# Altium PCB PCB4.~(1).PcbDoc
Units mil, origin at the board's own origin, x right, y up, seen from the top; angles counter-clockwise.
Board outline 6000 x 4000 mil, 2 copper layers (Top Layer, Bottom Layer); 86 components, 57 nets, 223 pads, 2 vias.
Unrouted connection lines stored in the file: 90.
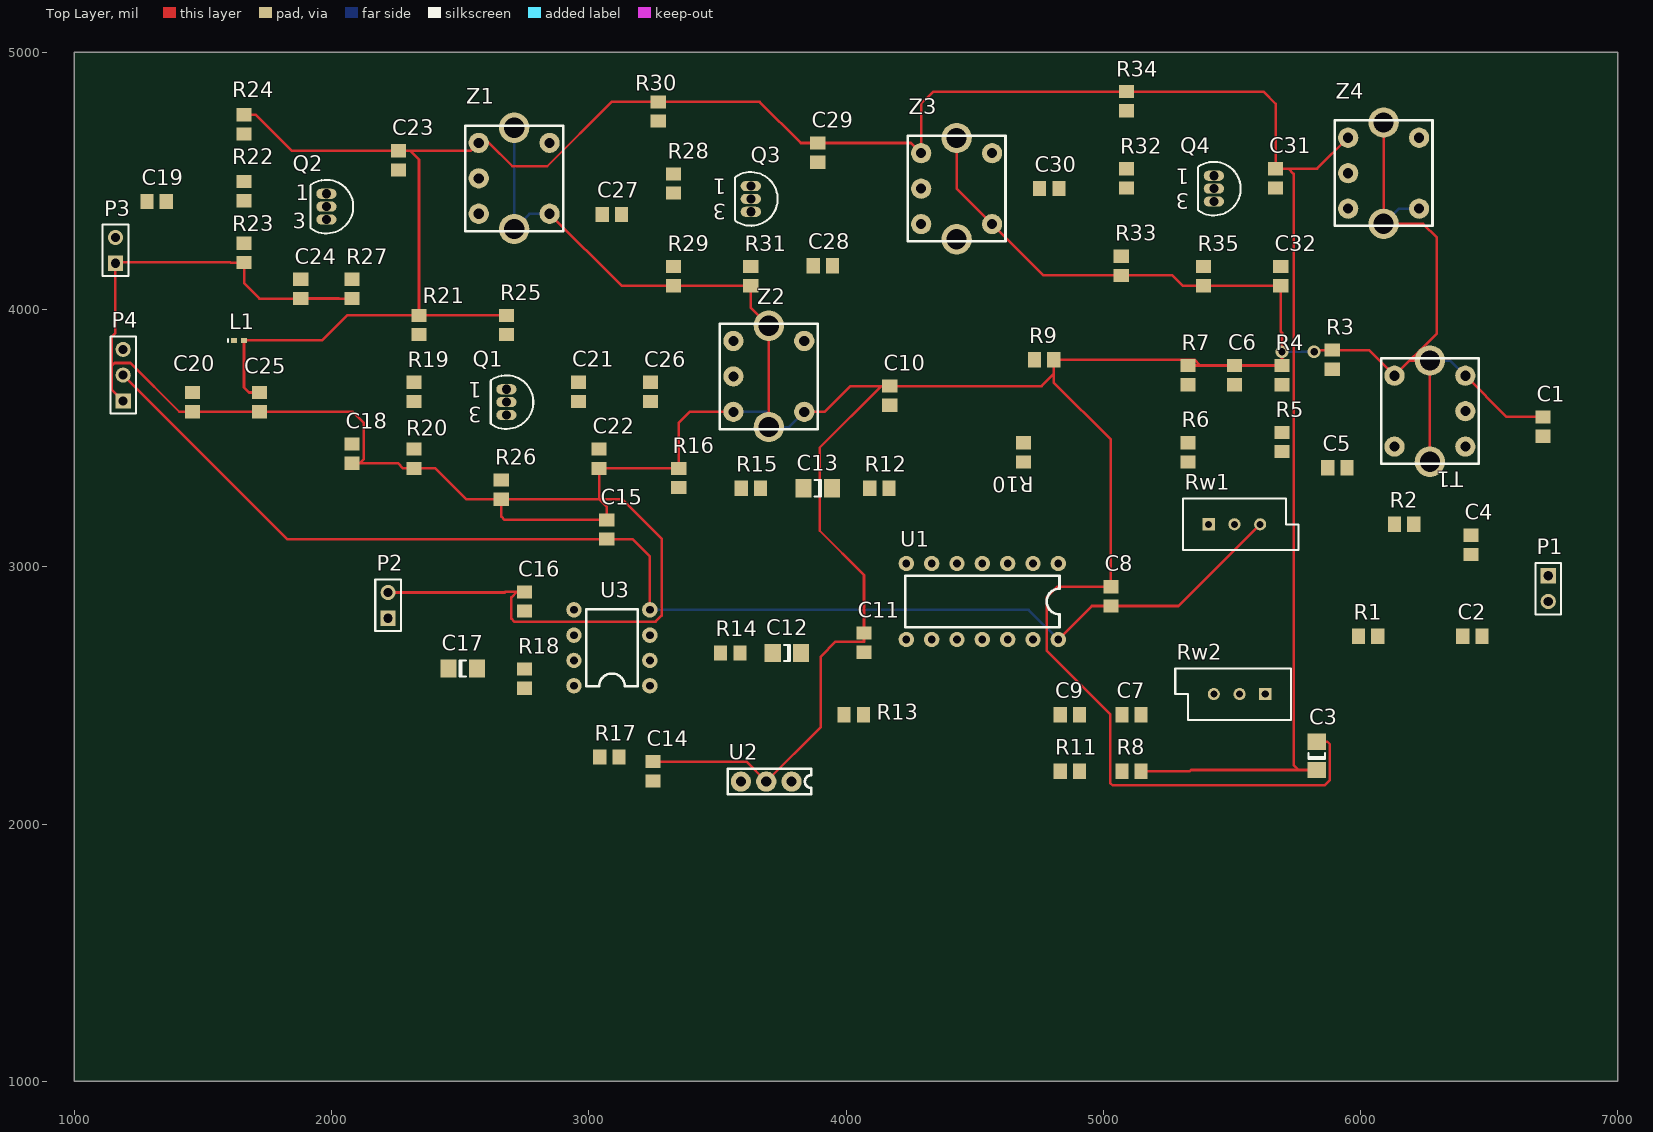
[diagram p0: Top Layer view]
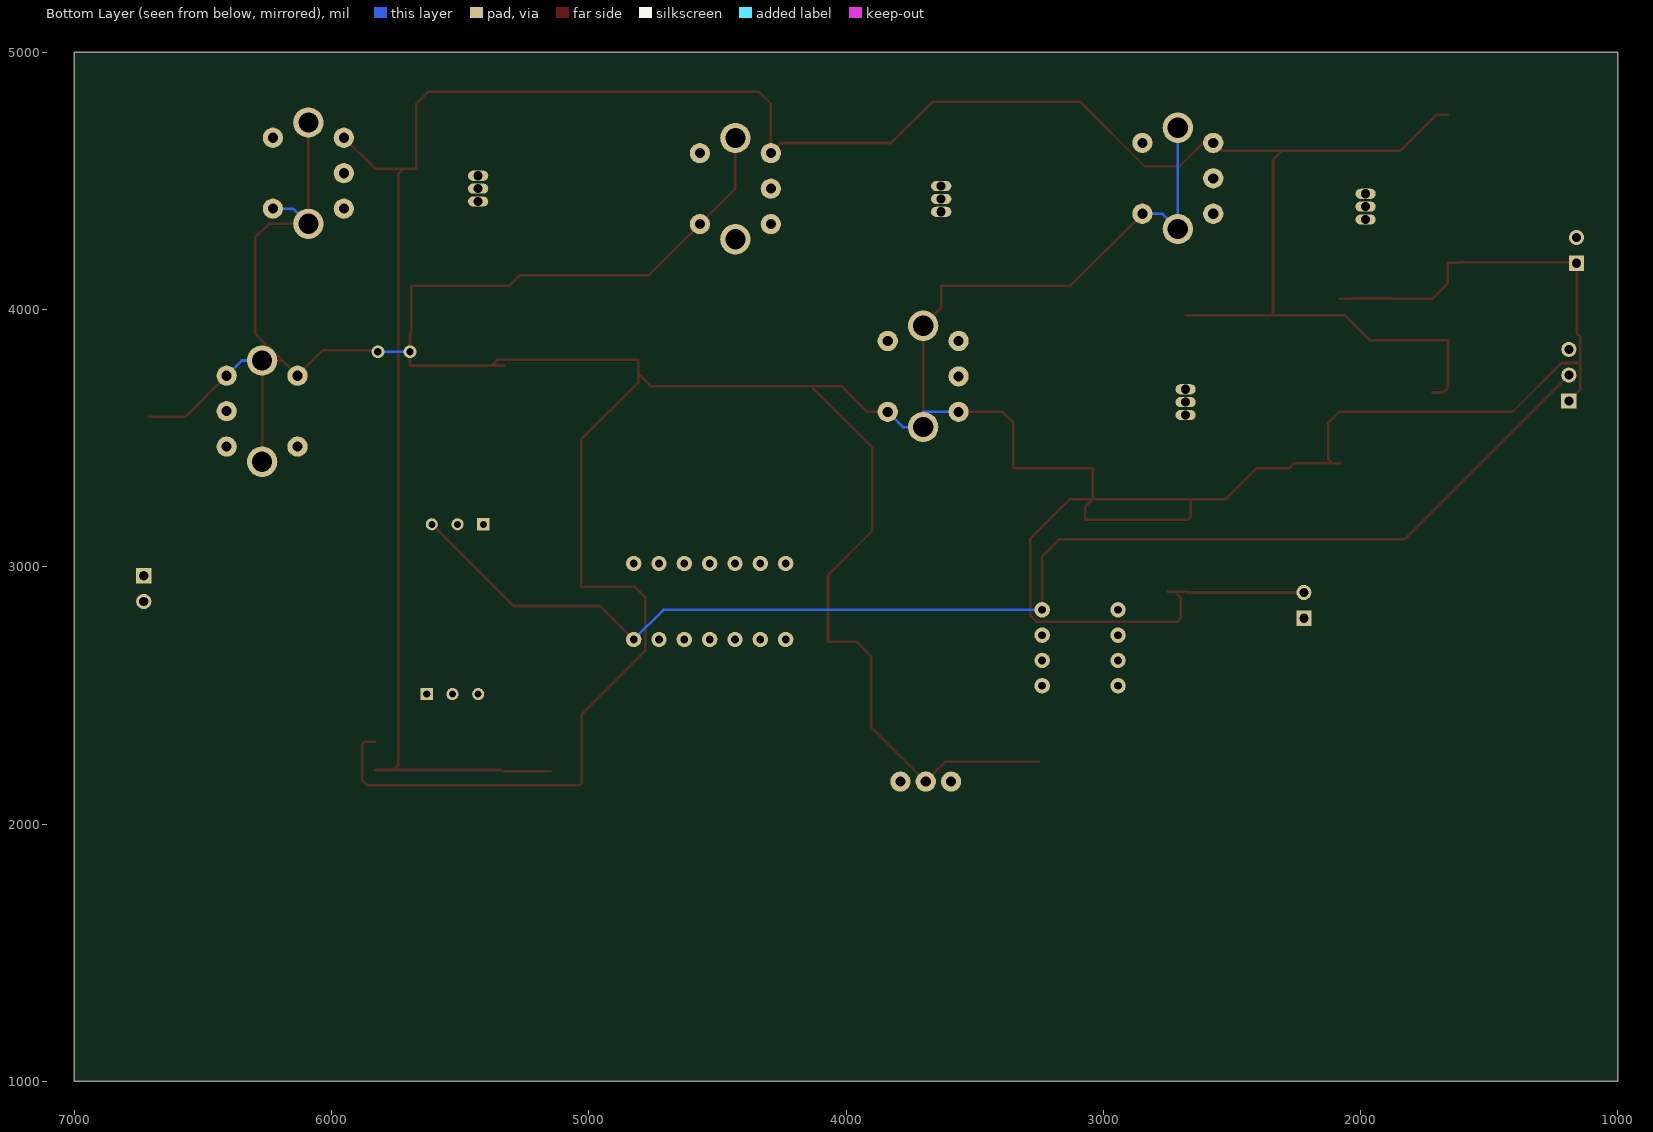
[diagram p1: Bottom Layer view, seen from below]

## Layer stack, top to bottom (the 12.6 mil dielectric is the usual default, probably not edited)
Top Layer: signal copper 1.4
Dielectric: dielectric 12.6, FR-4, Dk 4.8
Bottom Layer: signal copper 1.4

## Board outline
1000,1000 7000,1000 7000,5000 1000,5000

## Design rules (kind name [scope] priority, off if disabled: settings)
Clearance [All] p1: gap=10
PolygonConnect [All] p1: connectstyle=Relief reliefconductorwidth=10 reliefentries=4 polygonreliefangle="90 Angle"
RoomDefinition Sheet1 [InComponentClass('Sheet1')] p1: confinementstyle=ConfineIn formatcopy=TRUE lockcomponents=FALSE outline 0,0 2000,0 2000,1000 0,1000
RoomDefinition Sheet2 [InComponentClass('Sheet2')] p2: confinementstyle=ConfineIn formatcopy=TRUE lockcomponents=FALSE outline 0,0 2000,0 2000,1000 0,1000
RoutingVias [All] p1: holewidth=28 width=50 viastyle="Through Hole" minholewidth=28 minwidth=50 maxholewidth=28 maxwidth=50
SilkscreenOverComponentPads [All] p1: minsilkscreentomaskgap=10
SolderMaskExpansion [All] p1: expansion=4
TestPointUsage [All] p1: valid=0 allowmultiple=FALSE
Testpoint [All] p1: side=15 testpointundercomponent=TRUE minsize=40 maxsize=100 preferedsize=60 minholesize=0 maxholesize=40 preferedholesize=32 testpointgrid=1 style=1023 order=0123456789
Width [All] p1: maxlimit=10 minlimit=10 preferedwidth=10
23 further rules are at their usual default settings.

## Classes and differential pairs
component class Sheet2: C18 C19 C20 C21 C22 C23 C24 C25 C26 C27 C28 C29 C30 C31 C32 L1 P3 P4 Q1 Q2 Q3 Q4 R19 R20 R21 R22 R23 R24 R25 R26 R27 R28 R29 R30 R31 R32 R33 R34 R35 Z1 Z2 Z3 Z4
component class Sheet1: C1 C2 C3 C4 C5 C6 C7 C8 C9 C10 C11 C12 C13 C14 C15 C16 C17 P1 P2 R1 R2 R3 R4 R5 R6 R7 R8 R9 R10 R11 R12 R13 R14 R15 R16 R17 R18 Rw1 Rw2 T1 U1 U2 U3

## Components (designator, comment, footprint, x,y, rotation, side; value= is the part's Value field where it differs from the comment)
C1 "Cap" 2012[0805] 6710,3545 r270 top
C2 "Cap" 2012[0805] 6435,2730 r180 top
C3 "Cap Pol1" C1206 5830,2265 r90 top
C4 "Cap" 2012[0805] 6430,3085 r270 top
C5 "Cap" 2012[0805] 5910,3385 r180 top
C6 "Cap" 2012[0805] 5510,3745 r270 top
C7 "Cap" 2012[0805] 5110,2425 r180 top
C8 "Cap" 2012[0805] 5030,2885 r270 top
C9 "Cap" 2012[0805] 4870,2425 r180 top
C10 "Cap" 2012[0805] 4170,3665 r270 top
C11 "Cap" 2012[0805] 4070,2705 r270 top
C12 "Cap Pol1" C1206 3770,2665 r180 top
C13 "Cap Pol1" C1206 3890,3305 r180 top
C14 "Cap" 2012[0805] 3250,2205 r270 top
C15 "Cap" 2012[0805] 3070,3145 r270 top
C16 "Cap" 2012[0805] 2750,2865 r270 top
C17 "Cap Pol1" C1206 2510,2605 r0 top
C18 "Cap" 2012[0805] 2080,3440 r270 top
C19 "Cap" 2012[0805] 1320,4420 r0 top
C20 "Cap" 2012[0805] 1460,3640 r90 top
C21 "Cap" 2012[0805] 2960,3680 r270 top
C22 "Cap" 2012[0805] 3040,3420 r270 top
C23 "Cap" 2012[0805] 2260,4580 r270 top
C24 "Cap" 2012[0805] 1880,4080 r90 top
C25 "Cap" 2012[0805] 1720,3640 r90 top
C26 "Cap" 2012[0805] 3240,3680 r90 top
C27 "Cap" 2012[0805] 3090,4370 r0 top
C28 "Cap" 2012[0805] 3910,4170 r0 top
C29 "Cap" 2012[0805] 3890,4610 r270 top
C30 "Cap" 2012[0805] 4790,4470 r0 top
C31 "Cap" 2012[0805] 5670,4510 r270 top
C32 "Cap" 2012[0805] 5690,4130 r90 top
L1 "Inductor" 0402-A 1640,3880 r0 top
P1 "Header 2" HDR1X2 6730,2965 r270 top
P2 "Header 2" HDR1X2 2220,2800 r90 top
P3 "Header 2" HDR1X2 1160,4180 r90 top
P4 "Header 3" HDR1X3 1190,3645 r90 top
Q1 "NPN" TO-226 2680,3640 r180 top
Q2 "NPN" TO-226 1980,4400 r180 top
Q3 "NPN" TO-226 3630,4430 r180 top
Q4 "NPN" TO-226 5430,4470 r180 top
R1 "Res1" 2012[0805] 6030,2730 r180 top
R2 "Res1" 2012[0805] 6170,3165 r180 top
R3 "Res1" 2012[0805] 5890,3805 r270 top
R4 "Res1" 2012[0805] 5695,3745 r270 top
R5 "Res1" 2012[0805] 5695,3485 r270 top
R6 "Res1" 2012[0805] 5330,3445 r270 top
R7 "Res1" 2012[0805] 5330,3745 r270 top
R8 "Res1" 2012[0805] 5110,2205 r180 top
R9 "Res1" 2012[0805] 4770,3805 r180 top
R10 "Res1" 2012[0805] 4690,3445 r270 top
R11 "Res1" 2012[0805] 4870,2205 r180 top
R12 "Res1" 2012[0805] 4130,3305 r180 top
R13 "Res1" 2012[0805] 4030,2425 r180 top
R14 "Res1" 2012[0805] 3550,2665 r180 top
R15 "Res1" 2012[0805] 3630,3305 r180 top
R16 "Res1" 2012[0805] 3350,3345 r270 top
R17 "Res1" 2012[0805] 3080,2260 r180 top
R18 "Res1" 2012[0805] 2750,2565 r270 top
R19 "Res1" 2012[0805] 2320,3680 r90 top
R20 "Res1" 2012[0805] 2320,3420 r90 top
R21 "Res Adj1" 2012[0805] 2340,3940 r270 top
R22 "Res1" 2012[0805] 1660,4460 r90 top
R23 "Res1" 2012[0805] 1660,4220 r90 top
R24 "Res Adj1" 2012[0805] 1660,4720 r270 top
R25 "Res1" 2012[0805] 2680,3940 r90 top
R26 "Res1" 2012[0805] 2660,3300 r90 top
R27 "Res1" 2012[0805] 2080,4080 r90 top
R28 "Res1" 2012[0805] 3330,4490 r90 top
R29 "Res1" 2012[0805] 3330,4130 r90 top
R30 "Res Adj1" 2012[0805] 3270,4770 r270 top
R31 "Res1" 2012[0805] 3630,4130 r90 top
R32 "Res1" 2012[0805] 5090,4510 r90 top
R33 "Res1" 2012[0805] 5070,4170 r90 top
R34 "Res Adj1" 2012[0805] 5090,4810 r270 top
R35 "Res1" 2012[0805] 5390,4130 r90 top
Rw1 "RPot" VR5 5510,3165 r0 top
Rw2 "RPot" VR5 5530,2505 r180 top
T1 "zhongzhou" zhongzhou 6270,3605 r180 top
U1 "MC1496" MC1496 4530,2865 r180 top
U2 "LM7808" LM7808 3690,2165 r180 top
U3 "LM741" LM741 3090,2685 r180 top
Z1 "zhongzhou1" zhongzhou 2710,4510 r0 top
Z2 "zhongzhou4" zhongzhou 3700,3740 r0 top
Z3 "zhongzhou2" zhongzhou 4430,4470 r0 top
Z4 "zhongzhou3" zhongzhou 6090,4530 r0 top

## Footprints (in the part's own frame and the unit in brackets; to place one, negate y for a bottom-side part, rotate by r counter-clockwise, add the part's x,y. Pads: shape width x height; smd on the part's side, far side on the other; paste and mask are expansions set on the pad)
0402-A [mm] "Chip Inductor; Body 1 x 0.5 mm (LxW typ)"
  rect 0.6x0.5 smd: 1(-0.5,0) 2(0.5,0)
  silkscreen extent -1.1,-0.15 -1.1,0.15
2012[0805] [mm] "Chip Resistor; Body 2.0 x 1.3 mm (LxW typ)"
  rect 1.3x1.5 smd: 1(-0.95,0) 2(0.95,0)
C1206 [mm] "Chip Capacitor; Body 3.2 x 1.6 mm (LxW typ)"
  rect 1.6x1.8 smd: 1(-1.4,0) 2(1.4,0)
  silkscreen extent -0.3,-0.8 0.3,0.8
HDR1X2 [mm] "Connector; Header; 2 Position"
  rect 1.5x1.5 hole 0.9: 1(0,0)
  round 1.5 hole 0.9: 2(2.54,0)
  silkscreen extent -1.27,-1.27 3.81,1.27
HDR1X3 [mm] "Connector; Header; 3 Position"
  rect 1.5x1.5 hole 0.9: 1(0,0)
  round 1.5 hole 0.9: 2(2.54,0) 3(5.08,0)
  silkscreen extent -1.27,-1.27 6.35,1.27
LM741 [mil]
  round 60 hole 30: 1(-147.64,147.64) 2(-147.64,49.21) 3(-147.64,-49.21) 4(-147.64,-147.64) 5(147.64,-147.64) 6(147.64,-49.21) 7(147.64,49.21) 8(147.64,147.64)
  silkscreen extent -100,-150 100,150
LM7808 [mm]
  round 2 hole 1: 1(-2.5,0) 2(0,0) 3(2.5,0)
  silkscreen extent -4.44,-1.27 3.81,1.27
MC1496 [mil]
  round 60 hole 30: 1(-295.28,-147.64) 2(-196.85,-147.64) 3(-98.43,-147.64) 4(0,-147.64) 5(98.43,-147.64) 6(196.85,-147.64) 7(295.28,-147.64) 8(295.28,147.64) 9(196.85,147.64) 10(98.43,147.64) 11(0,147.64) 12(-98.43,147.64) 13(-196.85,147.64) 14(-295.28,147.64)
  silkscreen extent -300,-100 300,100
TO-226 [mm] "TO, Flat Index; 3 In-Line, Axial Leads; Body Dia. 4.8mm; Leads 0.55 x 0.51 mm (max)"
  oval 2x1 hole 0.9: 1(0,-1.27) 2(0,0) 3(0,1.27)
  silkscreen extent -2.65,-2.65 1.55,2.65
VR5 [mm] "Potentiometer; 3 Leads"
  rect 1.2x1.2 hole 0.7: 1(-2.54,0)
  round 1.2 hole 0.7: 2(0,0) 3(2.54,0)
  silkscreen extent -5.08,-2.54 6.35,2.54
zhongzhou [mm]
  round 2 hole 1: 1(-3.5,3.5) 2(-3.5,0) 3(-3.5,-3.5) 4(3.5,-3.5) 5(3.5,3.5)
  round 3 hole 2: 6(0,5) 7(0,-5)
  silkscreen extent -4.83,-5.21 4.83,5.21

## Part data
C1 C2 C4 C5 C6 C7 C8 C9 C10 C11 C14 C15 C16 C18 C19 C20 C21 C22 C23 C24 C25 C26 C27 C28 C29 C30 C31 C32: "Capacitor"
C3 C12 C13 C17: "Polarized Capacitor (Radial)"
P1 P2 P3: "Header, 2-Pin"
P4: "Header, 3-Pin"
Q1 Q2 Q3 Q4: "NPN Bipolar Transistor"
R1 R2 R3 R4 R5 R6 R7 R8 R9 R10 R11 R12 R13 R14 R15 R16 R17 R18 R19 R20 R22 R23 R25 R26 R27 R28 R29 R31 R32 R33 R35: "Resistor"
R21 R24 R30 R34: "Variable Resistor"
Rw1 Rw2: "Potentiometer"

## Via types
v1: diameter 50, hole 28, Top Layer to Bottom Layer, 2 vias

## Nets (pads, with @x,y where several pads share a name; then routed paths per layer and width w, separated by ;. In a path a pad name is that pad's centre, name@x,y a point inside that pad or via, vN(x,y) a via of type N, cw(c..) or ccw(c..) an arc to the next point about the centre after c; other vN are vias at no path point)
+12V: C3.1 C23.1 C25.2 C29.1 C31.1 L1.2 R8.1 R21.1 R24.1 R25.2 R30.1 R34.1 Z1.1 Z3.1 Z4.1 | length 10221.8
  Top Layer w10: R24.1 1705,4757.4 1845,4617.4 C23.1 ; C25.2 1680,3677.4 1659.69,3697.72 L1.2 1963,3880 2060.4,3977.4 R21.1 ; R25.2 2680,3978 R21.1@2340,3978 ; R8.1 5337,2205 5341.88,2209.88 5760,2209.88 ; C3.1 5760,2209.88 ; Z4.1 5831.81,4547.4 5720,4547.4 ; C23.1 2305,4617.4 ; C23.1 2305,4617.4 ; 2305,4617.4 2541.81,4617.4 Z1.1 2612,4647.8 2702.8,4557 2838.6,4557 3089,4807.4 R30.1 3664.6,4807.4 3824.6,4647.4 C29.1 4252.6,4647.4 Z3.1 4292.2,4800 4339.61,4847.4 R34.1 5622.6,4847.4 5670,4800 C31.1 ; 2305,4617.4 2340,4582.4 R21.1@2340,3978 ; R21.1 R21.1@2340,3978 ; R21.1 R21.1@2340,3978 ; C31.1 5720,4547.4 ; C31.1 5720,4547.4 ; 5720,4547.4 5740,4527.4 5740,2229.88 5760,2209.88
-8V: C8.2 C15.2 P4.2 Rw1.3 U1.14 U3.4 | length 5152.5
  Top Layer w10: P4.2 1827.4,3107.6 C15.2 3170.04,3107.6 3237.64,3040 U3.4 ; U1.14 4955.51,2847.6 C8.2 5292.6,2847.6 Rw1.3
  Bottom Layer w10: U3.4 4710,2832.64 U1.14
GND: C1.1 C3.2 C6.1 C8.1 C10.1 C11.1 C14.1 C15.1 C16.1 C18.2 C20.1 C22.2 C24.1 C25.1 C32.1 P2.2 P3.1 P4.1 R3.1 R4.1 R7.1 R9.1 R16.1 R20.1 R23.1 R26.1 R27.1 R29.1 R31.1 R33.1 R35.1 T1.3 T1.4 T1.6 T1.7 U2.2 Z1.4 Z1.6 Z1.7 Z2.3 Z2.4 Z2.6 Z2.7 Z3.4 Z3.6 Z4.4 Z4.6 Z4.7 | length 22173.2
  Top Layer w10: P4.1 1145,3690 ; R27.1 2028.4,4042.6 2028,4043 1880,4043 C24.1 1720,4042.6 1660,4102.6 R23.1 1607.4,4182.6 1607,4183 1163,4183 P3.1 1160,3909 1145,3894 1145,3780 ; P2.2 2673,2900 2675.4,2902.4 2720,2902.4 ; Z1.4 3127.4,4092.6 R29.1 3330,4093 3461,4093 3461.4,4092.6 R31.1 3630,4006.85 Z2.6 Z2.7 ; C14.1 3612.6,2242.4 U2.2 3902,2377 3902,2651 3960,2709 4070,2709 C11.1 4070,2968 3898,3140 3898,3463 4137.4,3702.4 ; Z2.3 3392.2,3602.2 3350,3560 R16.1 3319,3382.4 3318.4,3383 3105,3383 3104.6,3382.6 C22.2 3040,3263 3040.4,3262.6 ; Z2.4 3917.2,3602.2 4017.4,3702.4 4137.4,3702.4 ; Z3.6 4430,4470 Z3.4 4767.4,4132.6 R33.1 5268.4,4132.6 5308.4,4092.6 R35.1 C32.1 5690,3914 5695,3909 v1(5695,3836) ; v1(5820,3836) 5826.4,3842.4 R3.1 6032.6,3842.4 T1.4 ; C3.2 5870.88,2320.12 5881,2310 5881,2171 5860,2150 5037,2150 5027,2160 5027,2427 4780,2674 4780,2880 4823,2923 4976,2923 4976.6,2922.4 C8.1 5030,3494 4807.4,3716.6 4807.4,3749.8 ; Z4.6 Z4.7 6243.85,4333.15 6297,4280 6297,3907.59 6230.63,3841.22 6191.26,3801.85 ; T1.6 T1.7 6191.26,3801.85 ; T1.3 6568.19,3582.4 C1.1 ; 1145,3690 1145,3780 ; 1145,3690 1145,3780 ; 1145,3780 1157,3792 1218.6,3792 1408,3602.6 C20.1 C25.1 2082.4,3602.6 2125,3560 2125,3417.6 2110,3402.6 ; 2110,3402.6 2258,3402.6 2278,3382.6 R20.1 2403.4,3382.6 2523.4,3262.6 R26.1 ; 2110,3402.6 C18.2 2110,3402.6 ; R26.1 3040.4,3262.6 ; R26.1 2660,3195 2672.6,3182.4 C15.1 3070,3233 3040.4,3262.6 ; 2720,2902.4 C16.1 2720,2902.4 ; 2720,2902.4 2699,2881.4 2699,2798 2710,2787 3260,2787 3283,2810 3283,3109 3129.4,3262.6 3040.4,3262.6 ; 4137.4,3702.4 C10.1 ; 4137.4,3702.4 C10.1 ; C10.1 4760,3702.4 4807.4,3749.8 ; 4807.4,3749.8 R9.1 5330,3805 5354.4,3805 5377,3782.4 ; 5377,3782.4 C6.1 R4.1 ; 5377,3782.4 R7.1 5377,3782.4 ; R4.1 v1(5695,3836) ; R4.1 v1(5695,3836) ; T1.4 6191.26,3801.85 ; T1.4 6191.26,3801.85
  Bottom Layer w10: Z1.6 Z1.7 2769.05,4372.2 Z1.4 ; Z2.3 3563,3603 3700,3603 Z2.7 3778.74,3543.15 Z2.4 ; v1(5695,3836) v1(5820,3836) ; Z4.7 6149.05,4392.2 Z4.4 ; T1.7 6348.74,3801.85 T1.3
NetC1_2: C1.2 C4.1 R2.1 T1.1
NetC2_1: C2.1 P1.2
NetC2_2: C2.2 C4.2 R1.1
NetC5_1: C5.1 R2.2
NetC5_2: C5.2 R4.2 R5.1 U1.1
NetC6_2: C6.2 R6.1 R7.2 U1.4
NetC7_1: C7.1 Rw2.1 U1.8
NetC7_2: C7.2 C9.1 R8.2 R11.1 Rw2.3
NetC9_2: C9.2 R11.2
NetC10_2: C10.2 C13.1 R12.1 U1.6
NetC11_2: C11.2 C12.1 R13.1 U1.12
NetC12_2: C12.2 R14.1
NetC13_2: C13.2 R15.1
NetC14_2: C14.2 U2.3 U3.7
NetC16_2: C16.2 C17.1 R18.1
NetC17_2: C17.2 P2.1
NetC18_1: C18.1 Q1.2 R19.1 R20.2
NetC19_1: C19.1 P3.2
NetC19_2: C19.2 Q2.2 R22.1 R23.2
NetC20_2: C20.2 L1.1 P4.3
NetC21_1: C21.1 C26.2 Q1.1 R25.1
NetC21_2: C21.2 C22.1
NetC23_2: C23.2 Z1.3
NetC24_2: C24.2 Q2.3 R27.2
NetC26_1: C26.1 Z2.1
NetC27_1: C27.1 Z1.5
NetC27_2: C27.2 Q3.2 R28.1 R29.2
NetC28_1: C28.1 Q3.3 R31.2
NetC28_2: C28.2 Z2.5
NetC29_2: C29.2 Z3.3
NetC30_1: C30.1 Z3.5
NetC30_2: C30.2 Q4.2 R32.1 R33.2
NetC31_2: C31.2 Z4.3
NetC32_2: C32.2 Q4.3 R35.2
NetQ1_3: Q1.3 R26.2
NetQ2_1: Q2.1 Z1.2
NetQ3_1: Q3.1 Z3.2
NetQ4_1: Q4.1 Z4.2
NetR1_2: R1.2 Rw2.2 U1.10
NetR3_2: R3.2 T1.5
NetR5_2: R5.2 Rw1.2
NetR6_2: R6.2 Rw1.1
NetR9_2: R9.2 U1.5
NetR10_1: R10.1 U1.3
NetR10_2: R10.2 U1.2
NetR12_2: R12.2 R13.2 U2.1
NetR14_2: R14.2 R17.1 U3.2
NetR15_2: R15.2 R16.2 U3.3
NetR17_2: R17.2 R18.2 U3.6
NetR19_2: R19.2 R21.2
NetR22_2: R22.2 R24.2
NetR28_2: R28.2 R30.2
NetR32_2: R32.2 R34.2
ZHONGFANG: P1.1 Z4.5
pads on no net: T1.2 U1.7 U1.9 U1.11 U1.13 U3.1 U3.5 U3.8 Z2.2 Z3.7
